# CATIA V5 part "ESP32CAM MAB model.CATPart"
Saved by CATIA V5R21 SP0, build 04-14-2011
Part number: ESP32CAM MAB model
Bounding box of the stored display mesh (mm): x -13.5 to 13.5, y -20.25 to 20.25, z 0 to 10
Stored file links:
  C:\Users\pc\Desktop\PFA SIMULATION\ESP32CAM MAB model.CATPart
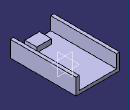
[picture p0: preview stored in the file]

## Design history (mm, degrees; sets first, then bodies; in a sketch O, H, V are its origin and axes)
Body1 (main body)
  Sketch1 on xy-plane, origin (0, 0, 0), H (1, 0, 0), V (0, 1, 0)
    line L1 (-13.5, 20.25) -> (13.5, 20.25)
    line L2 (13.5, 20.25) -> (13.5, -20.25)
    line L3 (13.5, -20.25) -> (-13.5, -20.25)
    line L4 (-13.5, -20.25) -> (-13.5, 20.25)
    length L1 = 27
    length L2 = 40.5
    distance L4 V = 13.5
    angle L1 L2 = 90
    distance L1 H = 20.25
    angle L3 L4 = 90
  Pad1: profile Sketch1, direction (0, 0, 1), length 2
  Sketch2 on end face of Pad1, origin (0, 0, 2), H (1, 0, 0), V (0, 1, 0)
    line L1 (11.5, 20.25) -> (13.5, 20.25)
    line L2 (13.5, 20.25) -> (13.5, -20.25)
    line L3 (13.5, -20.25) -> (11.5, -20.25)
    line L4 (11.5, -20.25) -> (11.5, 20.25)
    reference projected line E1 (13.5, 20.25) -> (-13.5, 20.25) from edge [face of Pad1 from Sketch1.L1 | end face of Pad1]
    line L5 (-11.5, 20.25) -> (-13.5, 20.25)
    line L6 (-13.5, 20.25) -> (-13.5, -20.25)
    line L7 (-13.5, -20.25) -> (-11.5, -20.25)
    line L8 (-11.5, -20.25) -> (-11.5, 20.25)
    length L1 = 2
    distance L2 V = 13.5
    length L2 = 40.5
    angle L4 L3 = 90
    angle L4 L1 = 90
    distance L1 E1 = 0
    distance L6 V = 13.5
    distance L5 E1 = 0
    angle L8 L7 = 90
    angle L8 L5 = 90
    length L6 = 40.5
    length L5 = 2
  Pad2: profile Sketch2, direction (0, 0, 1), length 8
  Sketch3 on end face of Pad1, origin (0, 0, 2), H (1, 0, 0), V (0, 1, 0)
    line L1 (-4.5, -20.25) -> (4.5, -20.25)
    line L2 (4.5, -20.25) -> (4.5, -12.85)
    line L3 (4.5, -12.85) -> (-4.5, -12.85)
    line L4 (-4.5, -12.85) -> (-4.5, -20.25)
    reference projected line E1 (-13.5, -20.25) -> (13.5, -20.25) from edge [face of Pad2 | end face of Pad1]
    reference projected line E2 (-13.5, 20.25) -> (-13.5, -20.25) from edge [face of Pad2 | end face of Pad2]
    distance L1 E1 = 0
    length L3 = 9
    length L2 = 7.4
    angle L3 L2 = 90
    angle L4 L3 = 90
    distance E2 L4 = 9
  Pad3: profile Sketch3, direction (0, 0, 1), length 3
  Sketch4 on face of Pad3, origin (0, -20.25, 0), H (1, 0, 0), V (0, 0, 1)
    line L1 (-4, 2.5) -> (4, 2.5)
    line L2 (4, 2.5) -> (4, 4.5)
    line L3 (4, 4.5) -> (-4, 4.5)
    line L4 (-4, 4.5) -> (-4, 2.5)
    reference projected line E1 (-13.5, 0) -> (13.5, 0) from edge [start face of Pad1 | face of Pad3]
    reference projected line E2 (-4.5, 2) -> (-4.5, 5) from edge [face of Pad3 | face of Pad3 from Sketch3.L4]
    reference projected line E3 (4.5, 2) -> (4.5, 5) from edge [face of Pad3 from Sketch3.L2 | face of Pad3]
    reference projected line E4 (-4.5, 5) -> (4.5, 5) from edge [face of Pad3 from Sketch3.L1 | end face of Pad3]
    distance L1 E1 = 2.5
    distance L4 E2 = 0.5
    distance L2 E3 = 0.5
    distance L3 E4 = 0.5
  Pocket1: profile Sketch4, direction (0, 1, 0), length 7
